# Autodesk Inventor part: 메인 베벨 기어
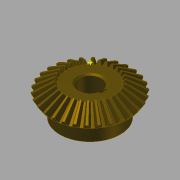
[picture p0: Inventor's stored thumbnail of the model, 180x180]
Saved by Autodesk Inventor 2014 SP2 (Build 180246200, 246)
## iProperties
Created: 2014-10
Part Number: 메인 베벨 기어
Material: 강철, 탄소
Document SubType Name: Modeling
Designer: KYOUNG IL JANG
Categories: <?xml version="1.0" encoding="UTF-16"?> <MemberInstance><Categories><FamilyTemplate><FamilyTemplateParameter ValueType="xs:double" Id="1" ObjectReferenceKey="da
Mass: 269.926 g
Surface Area: 108.837 cm^2
Volume: 34.2981 cm^3
Density: 7.87 g/cm^3
Appearance: 얼룩무늬
CustomPartVersion: 1
Author: SeoGD™ [www.esajin.kr]
Revision Number: 1
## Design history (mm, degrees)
node "맨 위 점"
node "메쉬 평면2"
sketch "톱니 본체 스케치"
  geometry: L1 (0, 0)-(28.669, -21.997); L2 (28.669, -21.997)-(31.109, -18.336); L3 (31.109, -18.336)-(0, 0); L4 (30, -20)-(0, 0); L5 (17.219, -13.212)-(18.685, -11.013); L6 (28.669, -21.997)-(17.219, -13.212); L7 (31.109, -18.336)-(18.685, -11.013); L8 (0, -39.387)-(0, 6.564) reference; L9 (0, -20)-(31.109, -20)
  constraints: 16 end point, 4 point on line, 3 perpendicular, 2 collinear, 1 horizontal alignment, 1 vertical alignment
  dimensions: "d0" = 60 diameter of L4.start L8 (= da_de); "d1" = 57.33744 diameter of L1.end L8 (= da_dfe); "d2" = 62.2188 diameter of L2.end L8 (= da_dae); "d3" = 14.4 distance between parallel lines of L2 L5 (= da_b); "d4" = 18.3359 vertical distance of L2.end L1.start (= da_ve)
revolve "톱니 본체" sketch "톱니 본체 스케치" stored, may be unused: angle "d5" = 90 deg
node "시작점"
node "톱니 평면"
sketch "시작 스케치"
  geometry: L1 (0, -23.505)-(0, 10.645) reference; L2 (-0.709, -2.928)-(0.709, -2.928); A1 r 19.188 centre (-19.457, -7.014) between (-0.709, -2.928) and (-3.232, 3.229); A2 r 19.188 centre (19.457, -7.014) between (3.232, 3.229) and (0.709, -2.928); A3 r 57.403 centre (0, -54.083) between (3.232, 3.229) and (-3.232, 3.229); 1 further point
  constraints: 6 point on circle, 3 centre point, 3 symmetric about line, 2 end point, 1 coincident, 1 perpendicular, 1 other
  dimensions: "d7" = 19.18795 radius of A1 (= fd_rr); "d8" = 19.45712 horizontal distance of point (0, -54.083) A1.centre (= fd_x); "d9" = 47.06905 vertical distance of point (0, -54.083) A1.centre (= fd_y); "d57" = 57.40327 radius of A3 (= 0.5 x fd_dva + 0.3 x da_he); "d58" = 51.15527 distance from line of A3.centre L2 (= 0.5 x fd_dva - 1.12 x da_he)
node "끝점"
  node "끝 평면"
sketch "3D 스케치 오른쪽"
  node "Helical Curve Right" dims "d65" = 229.90621 (computed from da_dm, da_delta, da_beta), "d66" = 31.5, "d67" = 60 (= da_de), "d68" = -9.82794 (= -da_delta), "d69" = 8.10972 (computed from fd_loft, da_delta)
node "끝 평면 오른쪽"
sketch "끝 스케치 오른쪽"
  geometry: L1 (0, -41.54)-(0, 13.178) reference; L2 (-0.422, -1.69)-(0.422, -1.69); A1 r 11.427 centre (-11.587, -4.123) between (-0.422, -1.69) and (-1.925, 1.977); A2 r 11.427 centre (11.587, -4.123) between (1.925, 1.977) and (0.422, -1.69); A3 r 34.184 centre (0, -32.153) between (1.925, 1.977) and (-1.925, 1.977); 1 further point
  constraints: 6 point on circle, 3 centre point, 3 symmetric about line, 2 end point, 1 coincident, 1 perpendicular, 1 other
  dimensions: "d70" = 11.58699 horizontal distance of A3.centre A1.centre (computed from fd_x, fd_ratio); "d71" = 28.03028 vertical distance of point (0, -32.153) A1.centre (computed from fd_y, fd_ratio); "d72" = 11.4267 radius of A1 (computed from fd_rr, fd_ratio); "d73" = 30.46369 distance from line of point (0, -32.153) L2 (computed from d58, fd_ratio); "d74" = 34.18446 radius of A3 (computed from d57, fd_ratio)
feature "로프트 오른쪽" sketch "끝 스케치 오른쪽" dims "d75" = 0, "d77" = 0, "d79" = 0, "d80" = 90 deg, "d85" = 20, "d92" = 90 deg, "d93" = 90 deg, "da_teethtype" = 0 [user parameter]
sketch "3D 스케치 왼쪽"
  node "Helical Curve Left" dims "d26" = 229.90621 (computed from da_dm, da_delta, da_beta), "d27" = 8.10972 (computed from fd_loft, da_delta), "d28" = 60 (= da_de), "d29" = -9.82794 (= -da_delta)
node "끝 평면 왼쪽"
sketch "끝 스케치 왼쪽" dims "d56" = 10.3728 (derived)
  geometry: L1 (0, -43.753)-(0, 15.405) reference; L2 (-0.422, -1.678)-(0.422, -1.678); A1 r 11.427 centre (-11.587, -4.111) between (-0.422, -1.678) and (-1.925, 1.988); A2 r 11.427 centre (11.587, -4.111) between (1.925, 1.988) and (0.422, -1.678); A3 r 34.184 centre (0, -32.142) between (1.925, 1.988) and (-1.925, 1.988); 2 further points; 1 other entity
  constraints: 6 point on circle, 3 centre point, 3 symmetric about line, 2 end point, 1 coincident, 2 other
  dimensions: "d30" = 11.4267 radius of A1 (computed from fd_rr, fd_ratio); "d31" = 11.58699 horizontal distance of point (0, -32.142) A1.centre (computed from fd_x, fd_ratio); "d32" = 28.03028 vertical distance of A1.centre point (0, -32.142) (computed from fd_y, fd_ratio); "d61" = 34.18446 radius of A3 (computed from d57, fd_ratio); "d62" = 30.46369 distance from line of point (0, -32.142) L2 (computed from d58, fd_ratio)
feature "로프트 왼쪽" sketch "끝 스케치 왼쪽" dims "d35" = 0, "d37" = 0, "d39" = 0, "d40" = 90 deg, "d84" = 10, "d90" = 90 deg, "d91" = 90 deg, "da_teethtype" = 0 [user parameter]
sketch "본체 스케치"
  geometry: L1 (0, -35.038)-(0, -19.531) reference; L2 (28.669, -21.997)-(17.219, -13.212) reference; L3 (17.219, -13.212)-(0, -13.212); L4 (28.669, -21.997)-(0, -21.997)
  constraints: 4 end point, 2 perpendicular, 2 point on line
revolve "본체 고정" sketch "본체 스케치" stored, may be unused: angle "d46" = 90 deg
feature "피치 지름" dims angle "d47" = 90 deg
sketch "스케치8"
  geometry: C1 r 22.5 at (0, 0); 1 further point
  constraints: 1 centre point, 1 coincident
  dimensions: "d94" = 45 diameter of C1
extrude "돌출1" join sketch "스케치8" distance "d95" = 13; taper "d96" = 0 deg
sketch "스케치9"
  geometry: 1 further point
hole "구멍1" sketch "스케치9" at (0, 0) diameter "d97" = 17; stored, may be unused: countersink angle "d101" = 90 deg, drill point angle "d103" = 118 deg; dims "d98" = 6, "d99" = 4, "d100" = 2, "d102" = 8
sketch "스케치10"
  geometry: L1 (8.124, 2.5)-(10.8, 2.5); L2 (10.8, 2.5)-(10.8, -2.5); L3 (10.8, -2.5)-(8.124, -2.5); A1 r 8.5 centre (0, 0) between (8.124, 2.5) and (8.124, -2.5) reference; 1 further point
  constraints: 6 end point, 2 parallel, 2 point on circle, 1 horizontal, 1 perpendicular
  dimensions: "d104" = 5 distance of L1.end L2.end; "d112" = 19.3 dimension on A1 L2
extrude "돌출2" cut sketch "스케치10" stored distance "d106" = 10; taper "d107" = 0 deg
chamfer "모따기1" distance "d108" = 1; stored, may be unused: second distance "d109" = 2, angle "d110" = 45 deg
fillet "모깎기1" dims "d111" = 2
body "Solid1"
feature "로프트" dims "d17" = 0, "d18" = 90 deg, "d19" = 0, "d20" = 90 deg, "d89" = 0, "da_teethtype" = 0 [user parameter]
pattern_circular "원형 패턴" dims angle "d22" = 360 deg, "d88" = 0, "da_teethtype" = 0 [user parameter]
pattern_circular "원형 패턴 오른쪽" dims angle "d82" = 360 deg, "da_teethtype" = 0 [user parameter]
pattern_circular "원형 패턴 왼쪽" dims angle "d42" = 360 deg, "da_teethtype" = 0 [user parameter]
sketch "끝 스케치"
  geometry: L1 (0, -15.359)-(0, 6.983) reference; L2 (-0.422, -1.69)-(0.422, -1.69); A1 r 11.427 centre (-11.587, -4.123) between (-0.422, -1.69) and (-1.925, 1.977); A2 r 11.427 centre (11.587, -4.123) between (1.925, 1.977) and (0.422, -1.69); A3 r 34.184 centre (0, -32.153) between (1.925, 1.977) and (-1.925, 1.977); 1 further point
  constraints: 6 point on circle, 3 centre point, 3 symmetric about line, 2 end point, 1 coincident, 1 other
  dimensions: "d12" = 11.4267 radius of A1 (computed from fd_rr, fd_ratio); "d15" = 11.58699 horizontal distance of A1.centre point (0, -32.153) (computed from fd_x, fd_ratio); "d16" = 28.03028 vertical distance of A1.centre point (0, -32.153) (computed from fd_y, fd_ratio); "d59" = 34.18446 radius of A3 (computed from d57, fd_ratio); "d60" = 30.46369 distance from line of A3.centre L2 (computed from d58, fd_ratio)
sketch "Sketch6"
  geometry: L1 (30, -20)-(0, 0) reference; L2 (0, -37.8)-(0, 6.3) reference
body "Srf1"
other parameters: "da_b" = 14.4 [user parameter; used in 2 equation terms], "da_de" = 60 [user parameter; used in 4 equation terms], "da_dae" = 62.2188 [user parameter; used in 2 equation terms], "da_dfe" = 57.33744 [user parameter; used in 1 equation term], "da_le" = 36.05551 [user parameter; used in 1 equation term], "da_omega" = 90 deg [user parameter; used in 1 equation term], "da_beta" = 0 [user parameter; used in 2 equation terms], "da_delta" = 9.82794 [user parameter; used in 8 equation terms], "da_alpha" = 20 deg [user parameter; used in 2 equation terms], "da_he" = 4.4 [user parameter; used in 4 equation terms], "da_ve" = 18.3359 [user parameter; used in 1 equation term], "fd_dv" = 108.16654 (computed from da_de, da_delta) [user parameter; used in 1 equation term], "fd_dva" = 112.16654 (computed from da_dae, da_delta) [user parameter; used in 3 equation terms], "fd_dvb" = 101.6433 (computed from fd_dv, da_alpha) [user parameter; used in 2 equation terms], "da_zv" = 540.83269 [user parameter; used in 1 equation term], "fd_loft" = 14.62 (= da_b + 0.05 x da_he) [user parameter; used in 4 equation terms], "fd_ratio" = 5.95514 (computed from da_le, fd_loft) [user parameter; used in 15 equation terms], "fd_rr" = 19.18795 (computed from fd_dd, fd_dvb) [user parameter; used in 6 equation terms], "fd_angle" = 0.29367 (computed from da_zv) [user parameter; used in 4 equation terms], "fd_x1" = 1.58802 (computed from da_dvw, fd_angle) [user parameter; used in 1 equation term], "fd_y1" = 54.05995 (computed from da_dvw, fd_angle) [user parameter; used in 1 equation term], "fd_x2" = 17.8691 (computed from fd_rr, fd_angle2, fd_angle) [user parameter; used in 1 equation term], "fd_y2" = 6.9909 (computed from fd_rr, fd_angle2, fd_angle) [user parameter; used in 1 equation term], "fd_x" = 19.45712 (= fd_x1 + fd_x2) [user parameter; used in 4 equation terms], "fd_y" = 47.06905 (= fd_y1 - fd_y2) [user parameter; used in 4 equation terms], "fd_angle2" = 3.43555 (computed from fd_dvb, fd_dd, da_alpha) [user parameter; used in 2 equation terms], "fd_dd" = 108.64654 (= fd_dva - 0.8 x da_he) [user parameter; used in 2 equation terms], "da_dvw" = 108.16654 [user parameter; used in 2 equation terms], "d11" = 14.62 (= fd_loft), "da_dm" = 48.01848 [user parameter; used in 2 equation terms], "da_x" = 0 [user parameter], "da_m" = 2 [user parameter], "d48" = 0, "d49" = 0, "d50" = 90 deg (= da_omega), "d51" = 6 deg (computed from da_z), "d52" = 0, "d53" = 0, "d54" = 0
